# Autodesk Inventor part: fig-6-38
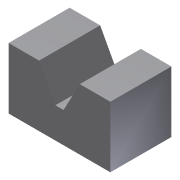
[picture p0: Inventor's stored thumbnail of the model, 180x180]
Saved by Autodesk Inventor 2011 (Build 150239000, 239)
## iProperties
Created: 2005-12
Part Number: fig-6-38
Document SubType Name: Modeling
Designer: CADCIM
Density: 1 g/cm^3
Author: CADCIM
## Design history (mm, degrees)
sketch "Sketch1"
  geometry: L1 (10, 15)-(25, 15); L2 (25, 15)-(25, -15); L3 (25, -15)-(-25, -15); L4 (-25, -15)-(-25, 15); L5 (-25, 15)-(-10, 15); L6 (-10, 15)-(-2, 0); L7 (-2, 0)-(2, 0); L8 (2, 0)-(10, 15); 1 further point
  constraints: 16 end point, 3 equal length, 3 parallel, 1 collinear, 1 horizontal, 1 perpendicular, 1 other
  dimensions: "d0" = 50 distance of L2.end L3.end; "d1" = 25 distance from line of point (0, 0) L2; "d2" = 30 distance of L1.end L2.end; "d3" = 15 distance of L1.start L1.end; "d4" = 15 distance between parallel lines of L1 L7; "d5" = 4 distance of L6.end L7.end; "d6" = 15 distance from line of point (0, 0) L3
extrude "Extrusion1" new body sketch "Sketch1" stored distance "d7" = 30; taper "d8" = 0 deg
body "Solid1"
